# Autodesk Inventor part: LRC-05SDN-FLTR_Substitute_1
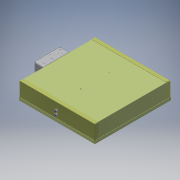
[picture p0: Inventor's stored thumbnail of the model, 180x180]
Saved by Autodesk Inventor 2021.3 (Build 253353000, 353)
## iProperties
Part Number: LRC-05SDN-FLTR_Substitute_1
Material: Generic
Document SubType Name: Modeling
Designer: JChurch
Manufacturer: Standard
Standards Organization: Custom
Density: 1 g/cm^3
Appearance: Smooth - Black
Author: JChurch
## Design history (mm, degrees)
derived "LRC-05SDN-FLTR.iam"
body "Solid9"
node "830399-00-00.ipt:1"
node "885000-00-00.iam:1::830000-00-00.ipt:1"
body "Solid10"
node "885000-00-00.iam:1::509424-00-00.ipt:1"
body "Solid11"
node "885000-00-00.iam:1::830593-00-00.ipt:1"
body "Solid12"
node "885000-00-00.iam:1::506002-00-00.ipt:1"
body "Solid13"
node "885000-00-00.iam:1::506002-00-00.ipt:2"
body "Solid14"
node "885000-00-00.iam:1::506002-00-00.ipt:3"
body "Solid15"
node "885000-00-00.iam:1::506002-00-00.ipt:4"
body "Solid16"
node "885000-00-00.iam:1::506002-00-00.ipt:5"
body "Solid17"
node "885000-00-00.iam:1::506002-00-00.ipt:6"
body "Solid18"
node "885000-00-00.iam:1::506002-00-00.ipt:7"
body "Solid19"
node "885000-00-00.iam:1::506002-00-00.ipt:8"
body "Solid20"
node "885000-00-00.iam:1::506002-00-00.ipt:9"
body "Solid21"
node "885000-00-00.iam:1::506002-00-00.ipt:10"
body "Solid22"
node "885000-00-00.iam:1::506002-00-00.ipt:11"
body "Solid23"
node "885000-00-00.iam:1::506002-00-00.ipt:12"
body "Solid24"
node "885000-00-00.iam:1::506002-00-00.ipt:13"
body "Solid25"
node "885000-00-00.iam:1::506002-00-00.ipt:14"
body "Solid26"
node "885000-00-00.iam:1::500027-00-00.ipt:1"
body "Solid27"
node "885000-00-00.iam:1::500027-00-00.ipt:2"
body "Solid28"
node "885000-00-00.iam:1::502116-00-00.ipt:1"
body "Solid29"
node "885000-00-00.iam:1::502116-00-00.ipt:2"
body "Solid30"
node "885000-00-00.iam:1::501030-00-00.ipt:1"
body "Solid31"
node "885000-00-00.iam:1::501030-00-00.ipt:2"
body "Solid32"
node "885000-00-00.iam:1::501030-00-00.ipt:3"
body "Solid33"
node "885000-00-00.iam:1::501030-00-00.ipt:4"
body "Solid34"
node "885000-00-00.iam:1::500027-00-00.ipt:3"
body "Solid35"
node "885000-00-00.iam:1::500027-00-00.ipt:4"
body "Solid36"
node "885000-00-00.iam:1::501030-00-00.ipt:5"
body "Solid37"
node "885000-00-00.iam:1::500027-00-00.ipt:5"
body "Solid38"
node "885000-00-00.iam:1::501030-00-00.ipt:6"
body "Solid39"
node "885000-00-00.iam:1::500027-00-00.ipt:6"
body "Solid40"
node "885000-00-00.iam:1::830593-00-00.ipt:2"
body "Solid41"
node "885000-00-00.iam:1::507032-00-00.ipt:1"
body "Solid42"
node "885000-00-00.iam:1::640042-00-03.ipt:1"
body "Solid43"
node "885000-00-00.iam:1::501030-00-00.ipt:9"
body "Solid44"
node "885000-00-00.iam:1::501030-00-00.ipt:10"
body "Solid45"
node "885000-00-00.iam:1::501030-00-00.ipt:11"
body "Solid46"
node "885000-00-00.iam:1::501030-00-00.ipt:12"
body "Solid47"
node "885000-00-00.iam:1::503031-00-00.ipt:1"
body "Solid48"
node "885000-00-00.iam:1::503031-00-00.ipt:2"
body "Solid49"
node "885000-00-00.iam:1::509425-00-00.ipt:1"
body "Solid50"
node "750938-00-XX.iam:1::710086-00-31.ipt:1"
body "Solid51"
node "750938-00-XX.iam:1::507008-00-38.ipt:1"
body "Solid52"
node "750938-00-XX.iam:1::710156-00-00.ipt:1"
body "Solid53"
node "750938-00-XX.iam:1::700503-20-00.ipt:1"
body "Solid54"
node "750938-00-XX.iam:1::507008-00-38.ipt:2"
body "Solid55"
node "725075-02-00.ipt:1"
body "Solid56"
other parameters: "d15" = 61.595, "d16" = 9.525, "d17" = 9.525, "d35" = 5.08
